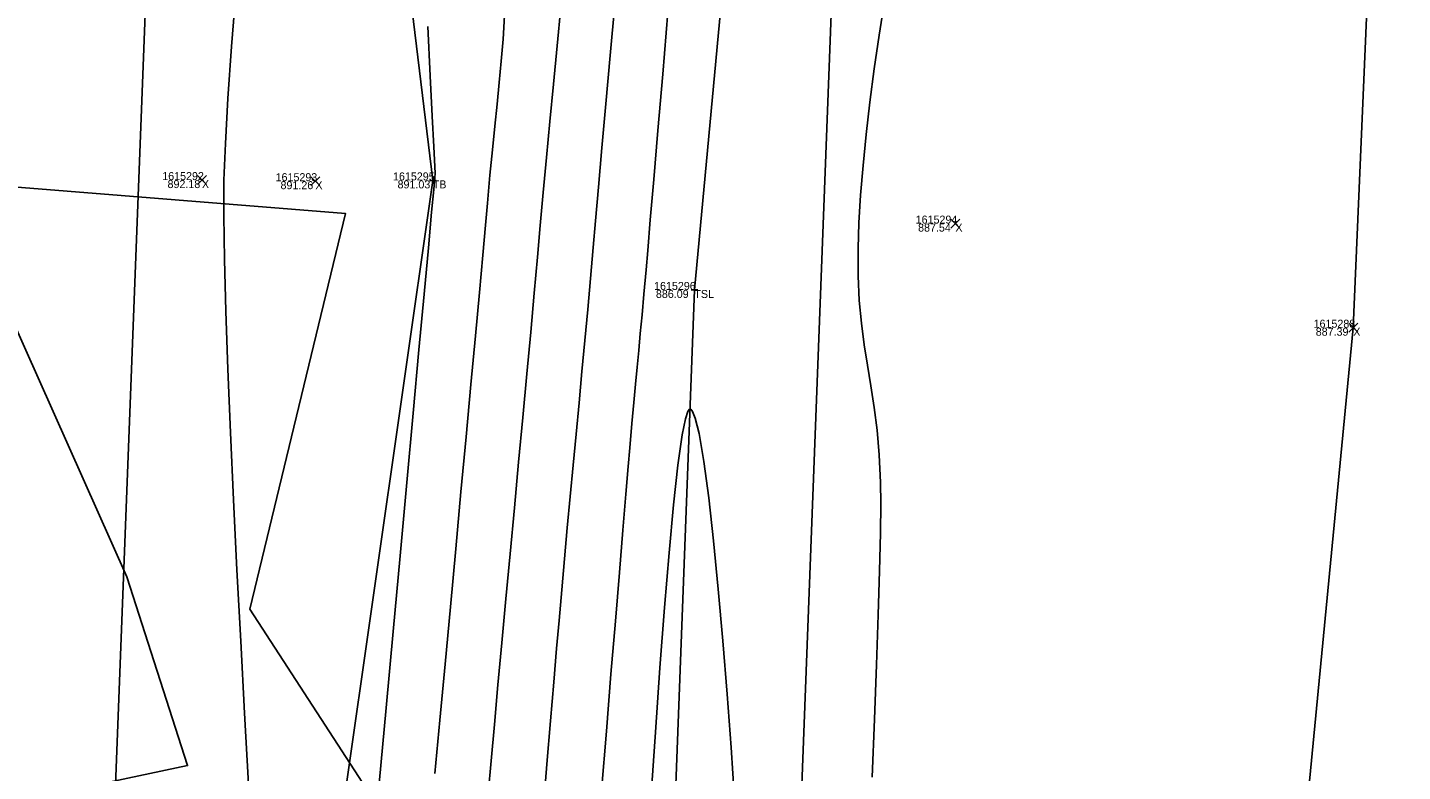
# Model space of a CAD drawing. Extents: x 1957117 to 1971063, y 701601 to 715861.
# Drawn here: x 1962717.9 to 1962778, y 702628.1 to 702660.6 of the extents above; entities that cross this region are included whole.
import ezdxf

# ---------------------------------------------------------------- set-up
doc = ezdxf.new("R2010")
doc.units = 0
for name, color, linetype in [('AP_X_Lights', 7, 'Continuous'), ('DT_X_Break_Line', 7, 'Continuous'), ('DT_X_Contour_Major', 7, 'Continuous'), ('DT_X_Contour_Minor', 7, 'Continuous'), ('DT_X_TIN_Hull', 7, 'Continuous'), ('GE_X_CL_20', 7, 'Continuous'), ('PV_P_Drive', 7, 'Continuous'), ('PV_P_Shoulder', 7, 'Continuous'), ('RS_Raster1', 7, 'Continuous'), ('RW_X_Esmt_RR', 7, 'Continuous'), ('SC_Scratch1', 7, 'Continuous'), ('VG_X_Tree_Line_Rt', 7, 'Continuous')]:
    doc.layers.add(name, color=color, linetype=linetype)

msp = doc.modelspace()

# ---------------------------------------------------------------- linework, layer by layer
at = {"layer": 'AP_X_Lights'}
for p, q in [((1962725.331, 702653.76), (1962725.719, 702654.15)), ((1962725.331, 702654.15), (1962725.719, 702653.76)), ((1962730.293, 702653.711), (1962730.681, 702654.101)), ((1962730.293, 702654.101), (1962730.681, 702653.711)), ((1962758.289, 702651.855), (1962758.677, 702652.245)), ((1962758.289, 702652.245), (1962758.677, 702651.855)), ((1962775.694, 702647.3), (1962776.082, 702647.69)), ((1962775.694, 702647.69), (1962776.082, 702647.3))]:
    msp.add_line(p, q, dxfattribs=at)
at = {"layer": 'DT_X_Break_Line'}
for points in [[(1962752.132, 702702.919), (1962747.065, 702649.147), (1962745.48, 702606.97), (1962743.008, 702552.829), (1962740.623, 702503.302), (1962740.641, 702452.933), (1962736.982, 702403.388), (1962741.529, 702352.919), (1962733.397, 702302.963), (1962742.046, 702251.987), (1962742.053, 702202.145), (1962741.582, 702152.179), (1962738.197, 702102.408), (1962725.619, 702053.061)], [(1962713.582, 702053.996), (1962711.466, 702104.13), (1962714.937, 702203.608), (1962720.713, 702253.951), (1962719.889, 702303.145), (1962721.566, 702358.521), (1962719.193, 702407.367), (1962722.415, 702453.828), (1962727.642, 702504.653), (1962726.923, 702553.596), (1962728.43, 702603.611), (1962735.623, 702653.941), (1962730.179, 702698.673)]]:
    msp.add_lwpolyline(points, dxfattribs=at)
at = {"layer": 'DT_X_Contour_Major'}
msp.add_lwpolyline([(1962738.761, 702661.155), (1962738.697, 702660.127), (1962738.621, 702659.158), (1962738.534, 702658.218), (1962738.439, 702657.278), (1962738.338, 702656.31), (1962738.231, 702655.283), (1962738.122, 702654.17), (1962738.011, 702652.941), (1962737.927, 702651.982), (1962737.809, 702650.663), (1962737.66, 702649.031), (1962737.487, 702647.133), (1962737.292, 702645.016), (1962737.081, 702642.726), (1962736.857, 702640.31), (1962736.626, 702637.816), (1962736.393, 702635.289), (1962736.161, 702632.778), (1962735.934, 702630.329), (1962735.719, 702627.988)], dxfattribs=at)
msp.add_lwpolyline([(1962738.761, 702661.155), (1962738.697, 702660.127), (1962738.621, 702659.158), (1962738.534, 702658.218), (1962738.439, 702657.278), (1962738.338, 702656.31), (1962738.231, 702655.283), (1962738.122, 702654.17), (1962738.011, 702652.941), (1962737.927, 702651.982), (1962737.809, 702650.663), (1962737.66, 702649.031), (1962737.487, 702647.133), (1962737.292, 702645.016), (1962737.081, 702642.726), (1962736.857, 702640.31), (1962736.626, 702637.816), (1962736.393, 702635.289), (1962736.161, 702632.778), (1962735.934, 702630.329), (1962735.719, 702627.988)], dxfattribs=at)
at = {"layer": 'DT_X_Contour_Minor'}
for points in [[(1962727.569, 702627.529), (1962727.392, 702630.635), (1962727.221, 702633.778), (1962727.058, 702636.907), (1962726.907, 702639.968), (1962726.773, 702642.909), (1962726.659, 702645.676), (1962726.57, 702648.216), (1962726.51, 702650.476), (1962726.482, 702652.404), (1962726.49, 702653.945), (1962726.549, 702655.551), (1962726.661, 702657.523), (1962726.82, 702659.805), (1962727.019, 702662.342)], [(1962727.569, 702627.529), (1962727.392, 702630.635), (1962727.221, 702633.778), (1962727.058, 702636.907), (1962726.907, 702639.968), (1962726.773, 702642.909), (1962726.659, 702645.676), (1962726.57, 702648.216), (1962726.51, 702650.476), (1962726.482, 702652.404), (1962726.49, 702653.945), (1962726.549, 702655.551), (1962726.661, 702657.523), (1962726.82, 702659.805), (1962727.019, 702662.342)], [(1962741.218, 702661.515), (1962741.06, 702659.824), (1962740.901, 702658.155), (1962740.744, 702656.521), (1962740.593, 702654.936), (1962740.452, 702653.415), (1962740.325, 702651.971), (1962740.204, 702650.576), (1962740.064, 702649.011), (1962739.909, 702647.304), (1962739.741, 702645.482), (1962739.564, 702643.573), (1962739.38, 702641.606), (1962739.193, 702639.608), (1962739.006, 702637.608), (1962738.822, 702635.633), (1962738.644, 702633.712), (1962738.474, 702631.872), (1962738.317, 702630.141), (1962738.175, 702628.548), (1962738.051, 702627.12)], [(1962741.218, 702661.515), (1962741.06, 702659.824), (1962740.901, 702658.155), (1962740.744, 702656.521), (1962740.593, 702654.936), (1962740.452, 702653.415), (1962740.325, 702651.971), (1962740.204, 702650.576), (1962740.064, 702649.011), (1962739.909, 702647.304), (1962739.741, 702645.482), (1962739.564, 702643.573), (1962739.38, 702641.606), (1962739.193, 702639.608), (1962739.006, 702637.608), (1962738.822, 702635.633), (1962738.644, 702633.712), (1962738.474, 702631.872), (1962738.317, 702630.141), (1962738.175, 702628.548), (1962738.051, 702627.12)], [(1962743.585, 702661.637), (1962743.387, 702659.401), (1962743.199, 702657.294), (1962743.025, 702655.36), (1962742.871, 702653.638), (1962742.74, 702652.172), (1962742.639, 702651.002), (1962742.522, 702649.653), (1962742.401, 702648.299), (1962742.276, 702646.939), (1962742.15, 702645.575), (1962742.021, 702644.209), (1962741.892, 702642.842), (1962741.763, 702641.474), (1962741.635, 702640.108), (1962741.508, 702638.744), (1962741.383, 702637.384), (1962741.262, 702636.03), (1962741.145, 702634.682), (1962741.042, 702633.464), (1962740.917, 702631.988), (1962740.775, 702630.288), (1962740.618, 702628.401), (1962740.45, 702626.363)], [(1962743.585, 702661.637), (1962743.387, 702659.401), (1962743.199, 702657.294), (1962743.025, 702655.36), (1962742.871, 702653.638), (1962742.74, 702652.172), (1962742.639, 702651.002), (1962742.522, 702649.653), (1962742.401, 702648.299), (1962742.276, 702646.939), (1962742.15, 702645.575), (1962742.021, 702644.209), (1962741.892, 702642.842), (1962741.763, 702641.474), (1962741.635, 702640.108), (1962741.508, 702638.744), (1962741.383, 702637.384), (1962741.262, 702636.03), (1962741.145, 702634.682), (1962741.042, 702633.464), (1962740.917, 702631.988), (1962740.775, 702630.288), (1962740.618, 702628.401), (1962740.45, 702626.363)], [(1962745.91, 702661.296), (1962745.681, 702658.588), (1962745.473, 702656.131), (1962745.29, 702653.986), (1962745.139, 702652.214), (1962745.025, 702650.876), (1962744.952, 702650.032), (1962744.86, 702648.968), (1962744.778, 702648.052), (1962744.702, 702647.244), (1962744.631, 702646.499), (1962744.561, 702645.776), (1962744.49, 702645.031), (1962744.415, 702644.223), (1962744.332, 702643.308), (1962744.24, 702642.243), (1962744.17, 702641.421), (1962744.068, 702640.205), (1962743.938, 702638.642), (1962743.784, 702636.779), (1962743.61, 702634.661), (1962743.419, 702632.334), (1962743.216, 702629.844), (1962743.004, 702627.239)], [(1962745.91, 702661.296), (1962745.681, 702658.588), (1962745.473, 702656.131), (1962745.29, 702653.986), (1962745.139, 702652.214), (1962745.025, 702650.876), (1962744.952, 702650.032), (1962744.86, 702648.968), (1962744.778, 702648.052), (1962744.702, 702647.244), (1962744.631, 702646.499), (1962744.561, 702645.776), (1962744.49, 702645.031), (1962744.415, 702644.223), (1962744.332, 702643.308), (1962744.24, 702642.243), (1962744.17, 702641.421), (1962744.068, 702640.205), (1962743.938, 702638.642), (1962743.784, 702636.779), (1962743.61, 702634.661), (1962743.419, 702632.334), (1962743.216, 702629.844), (1962743.004, 702627.239)], [(1962754.841, 702627.827), (1962754.941, 702630.367), (1962755.031, 702632.749), (1962755.106, 702634.929), (1962755.165, 702636.86), (1962755.204, 702638.499), (1962755.222, 702639.8), (1962755.214, 702640.717), (1962755.154, 702641.927), (1962755.055, 702643.014), (1962754.928, 702644.01), (1962754.785, 702644.946), (1962754.637, 702645.85), (1962754.496, 702646.753), (1962754.373, 702647.687), (1962754.279, 702648.68), (1962754.226, 702649.763), (1962754.225, 702650.967), (1962754.266, 702652.083), (1962754.339, 702653.297), (1962754.444, 702654.592), (1962754.579, 702655.955), (1962754.743, 702657.369), (1962754.934, 702658.818), (1962755.15, 702660.289), (1962755.39, 702661.765)], [(1962754.841, 702627.827), (1962754.941, 702630.367), (1962755.031, 702632.749), (1962755.106, 702634.929), (1962755.165, 702636.86), (1962755.204, 702638.499), (1962755.222, 702639.8), (1962755.214, 702640.717), (1962755.154, 702641.927), (1962755.055, 702643.014), (1962754.928, 702644.01), (1962754.785, 702644.946), (1962754.637, 702645.85), (1962754.496, 702646.753), (1962754.373, 702647.687), (1962754.279, 702648.68), (1962754.226, 702649.763), (1962754.225, 702650.967), (1962754.266, 702652.083), (1962754.339, 702653.297), (1962754.444, 702654.592), (1962754.579, 702655.955), (1962754.743, 702657.369), (1962754.934, 702658.818), (1962755.15, 702660.289), (1962755.39, 702661.765)], [(1962733.277, 702627.557), (1962733.579, 702630.858), (1962733.886, 702634.203), (1962734.19, 702637.517), (1962734.485, 702640.725), (1962734.763, 702643.752), (1962735.018, 702646.523), (1962735.242, 702648.963), (1962735.429, 702650.997), (1962735.572, 702652.549), (1962735.664, 702653.545), (1962735.697, 702653.91), (1962735.714, 702654.074), (1962735.723, 702654.237), (1962735.708, 702654.55), (1962735.666, 702655.405), (1962735.598, 702656.748), (1962735.51, 702658.523), (1962735.404, 702660.675)], [(1962733.277, 702627.557), (1962733.579, 702630.858), (1962733.886, 702634.203), (1962734.19, 702637.517), (1962734.485, 702640.725), (1962734.763, 702643.752), (1962735.018, 702646.523), (1962735.242, 702648.963), (1962735.429, 702650.997), (1962735.572, 702652.549), (1962735.664, 702653.545), (1962735.697, 702653.91), (1962735.714, 702654.074), (1962735.723, 702654.237), (1962735.708, 702654.55), (1962735.666, 702655.405), (1962735.598, 702656.748), (1962735.51, 702658.523), (1962735.404, 702660.675)], [(1962748.824, 702626.85), (1962748.669, 702629.125), (1962748.497, 702631.467), (1962748.309, 702633.802), (1962748.11, 702636.06), (1962747.904, 702638.168), (1962747.692, 702640.053), (1962747.48, 702641.645), (1962747.27, 702642.87), (1962747.105, 702643.538), (1962746.985, 702643.834), (1962746.907, 702643.924), (1962746.869, 702643.935), (1962746.838, 702643.923), (1962746.773, 702643.827), (1962746.672, 702643.515), (1962746.532, 702642.804), (1962746.348, 702641.485), (1962746.157, 702639.745), (1962745.961, 702637.645), (1962745.761, 702635.247), (1962745.56, 702632.611), (1962745.36, 702629.799), (1962745.162, 702626.872)], [(1962748.824, 702626.85), (1962748.669, 702629.125), (1962748.497, 702631.467), (1962748.309, 702633.802), (1962748.11, 702636.06), (1962747.904, 702638.168), (1962747.692, 702640.053), (1962747.48, 702641.645), (1962747.27, 702642.87), (1962747.105, 702643.538), (1962746.985, 702643.834), (1962746.907, 702643.924), (1962746.869, 702643.935), (1962746.838, 702643.923), (1962746.773, 702643.827), (1962746.672, 702643.515), (1962746.532, 702642.804), (1962746.348, 702641.485), (1962746.157, 702639.745), (1962745.961, 702637.645), (1962745.761, 702635.247), (1962745.56, 702632.611), (1962745.36, 702629.799), (1962745.162, 702626.872)]]:
    msp.add_lwpolyline(points, dxfattribs=at)
at = {"layer": 'DT_X_TIN_Hull'}
msp.add_lwpolyline([(1962757.576, 702251.621), (1962759.026, 702351.713), (1962754.137, 702402.367), (1962769.625, 702502.771), (1962771.847, 702605.545), (1962775.888, 702647.495), (1962778.042, 702697.695)], dxfattribs=at)
at = {"layer": 'GE_X_CL_20'}
msp.add_lwpolyline([(1962741.373, 703141.619), (1962697.729, 701998.272)], dxfattribs=at)
at = {"layer": 'PV_P_Drive'}
for p, q in [((1962735.623, 702654.087), (1962735.623, 702653.795)), ((1962735.477, 702653.941), (1962735.769, 702653.941)), ((1962735.623, 702653.941), (1962735.623, 702653.941)), ((1962747.065, 702649.293), (1962747.065, 702649.001)), ((1962746.919, 702649.147), (1962747.211, 702649.147)), ((1962747.065, 702649.147), (1962747.065, 702649.147))]:
    msp.add_line(p, q, dxfattribs=at)
at = {"layer": 'RW_X_Esmt_RR'}
msp.add_lwpolyline([(1962729.176, 702035.621), (1962771.351, 703140.475)], dxfattribs=at)
at = {"layer": 'VG_X_Tree_Line_Rt'}
msp.add_lwpolyline([(1962661.758, 702605.94), (1962693.037, 702605.672), (1962696.029, 702611.999), (1962697.914, 702621.319), (1962707.651, 702624.685), (1962724.898, 702628.339), (1962722.246, 702636.594), (1962714.524, 702653.874), (1962731.807, 702652.486), (1962727.617, 702635.179), (1962735.676, 702622.778), (1962721.735, 702611.35)], dxfattribs=at)

# ---------------------------------------------------------------- texts
at = {"layer": 'PV_P_Shoulder'}
for s, p in [('892.18', (1962724.021, 702653.605)), ('891.26', (1962728.963, 702653.556)), ('891.03', (1962734.083, 702653.591)), ('887.54', (1962756.852, 702651.7)), ('886.09', (1962745.384, 702648.797)), ('887.39', (1962774.246, 702647.145))]:
    msp.add_text(s, height=0.35, dxfattribs=at).set_placement(p)
at = {"layer": 'RS_Raster1'}
for s, p in [('1615292', (1962723.789, 702653.955)), ('1615293', (1962728.748, 702653.906)), ('1615295', (1962733.884, 702653.941)), ('1615294', (1962756.747, 702652.05)), ('1615296', (1962745.304, 702649.147)), ('1615288', (1962774.152, 702647.495))]:
    msp.add_text(s, height=0.35, dxfattribs=at).set_placement(p)
at = {"layer": 'SC_Scratch1'}
for s, p in [('X', (1962725.525, 702653.605)), ('X', (1962730.487, 702653.556)), ('TB', (1962735.623, 702653.591)), ('X', (1962758.483, 702651.7)), ('TSL', (1962747.065, 702648.797)), ('X', (1962775.888, 702647.145))]:
    msp.add_text(s, height=0.35, dxfattribs=at).set_placement(p)

doc.saveas('drawing.dxf')
